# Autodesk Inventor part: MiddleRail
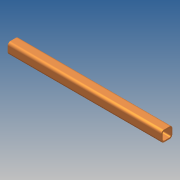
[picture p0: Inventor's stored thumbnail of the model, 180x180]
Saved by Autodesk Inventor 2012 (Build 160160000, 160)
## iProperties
Created: 2007-12
Part Number: MiddleRail
Document SubType Name: Modeling
Designer: MJ
Material: Aluminum-6061
Stock Number: D-623-012-a
Density: 2.71 g/cm^3
Engineer: MJ
Mass: 1975.9 g
Surface Area: 2316.93 cm^2
Volume: 729.116 cm^3
RuleStatus: InUse
Title: DgPr Assembly Cell
Author: MJ
Comments: 1.50" X 1.50" X 1/8" WALL TUBE X 19.81"
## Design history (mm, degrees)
sketch "Sketch2"
  geometry: L1 (-12.7, -25.4)-(12.7, -25.4); L2 (25.4, -12.7)-(25.4, 12.7); L3 (12.7, 25.4)-(-12.7, 25.4); L4 (-25.4, 12.7)-(-25.4, -12.7); L5 (-19.05, 12.7)-(-19.05, -12.7); L6 (-12.7, -19.05)-(12.7, -19.05); L7 (19.05, -12.7)-(19.05, 12.7); L8 (12.7, 19.05)-(-12.7, 19.05); A1 r 12.7 centre (12.7, 12.7) between (25.4, 12.7) and (12.7, 25.4); A2 r 12.7 centre (-12.7, 12.7) between (-12.7, 25.4) and (-25.4, 12.7); A3 r 12.7 centre (-12.7, -12.7) between (-25.4, -12.7) and (-12.7, -25.4); A4 r 12.7 centre (12.7, -12.7) between (12.7, -25.4) and (25.4, -12.7); A5 r 6.35 centre (-12.7, 12.7) between (-12.7, 19.05) and (-19.05, 12.7); A6 r 6.35 centre (-12.7, -12.7) between (-19.05, -12.7) and (-12.7, -19.05); A7 r 6.35 centre (12.7, -12.7) between (12.7, -19.05) and (19.05, -12.7); A8 r 6.35 centre (12.7, 12.7) between (19.05, 12.7) and (12.7, 19.05); 6 further points
  constraints: 16 end point, 16 point on circle, 8 centre point, 8 tangent, 6 point on line, 5 parallel, 3 equal radius, 2 horizontal alignment, 2 midpoint, 2 perpendicular, 2 vertical alignment, 1 horizontal, 8 other
extrude "Extrusion1" new body sketch "Sketch2" taper "d5" = 0 deg
body "Solid1"
